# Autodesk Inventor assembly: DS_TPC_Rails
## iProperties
Shininess: 64.0
Length Units: 11272
Angle Units: 11279
Time Units: 11290
Mass Units: 11286
Length Display Precision: 3
Angle Display Precision: 2
Compacted: True
Part Number: DS_TPC_Rails
Document SubType Name: Assembly
Created: 2004-08
Designer: Lori
Manufacturer: Standard
Standards Organization: Custom
Density: 0.0
Volumn: 0.0
Area: 0.0
PropertySet Name: Model Information
Control State: 0
Master: False
Checked Out: False
Author: Lori
